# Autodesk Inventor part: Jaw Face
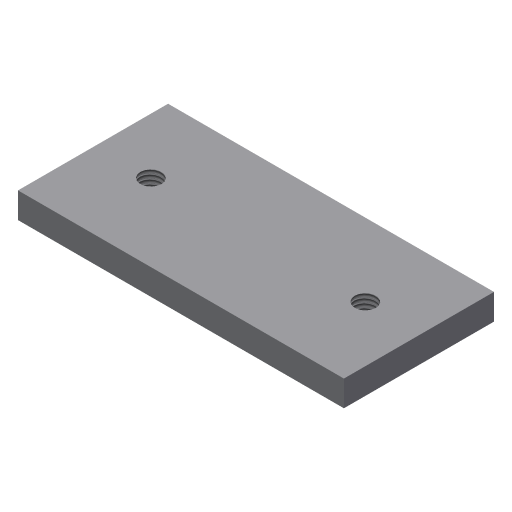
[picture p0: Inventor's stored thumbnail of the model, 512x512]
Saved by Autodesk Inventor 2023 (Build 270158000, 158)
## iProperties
Shininess: 77.0
Length Units: 11269
Angle Units: 11279
Time Units: 11290
Mass Units: 11283
Length Display Precision: 3
Angle Display Precision: 2
Compacted: True
Created: 2002-02
Part Number: Jaw Face
Document SubType Name: Modeling
Designer: ***
Density: 1 g/cm^3
Material: Generic
Mass: 15.6207 g
Surface Area: 67.651 cm^2
Volume: 15.6207 cm^3
Appearance: Default
Density: 0.0
Volumn: 0.0
Area: 0.0
PropertySet Name: Model Information
Control State: 0
Master: False
Checked Out: False
Author: ***
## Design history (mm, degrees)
sketch "Sketch1"
  geometry: L1 (-79.661, -8.43)-(-3.661, -8.43); L2 (-3.661, -8.43)-(-3.661, -43.43); L3 (-3.661, -43.43)-(-79.661, -43.43); L4 (-79.661, -43.43)-(-79.661, -8.43)
  constraints: 8 end point, 2 parallel, 1 horizontal, 1 perpendicular
  dimensions: "d0" = 76 distance of L2.end L3.end; "d3" = 35 distance of L1.end L2.end
extrude "Extrusion1" new body sketch "Sketch1" stored distance "d7" = 6; taper "d8" = 0 deg
hole "Hole1" diameter "d11" = 4.917; stored, may be unused: countersink angle "d15" = 90 deg, drill point angle "d17" = 118 deg; dims "d9" = 13, "d10" = 18, "d12" = 12, "d13" = 4, "d14" = 2, "d16" = 17.1
pattern_linear "Rectangular Pattern1" dims "d20" = -50
body "Solid1"
